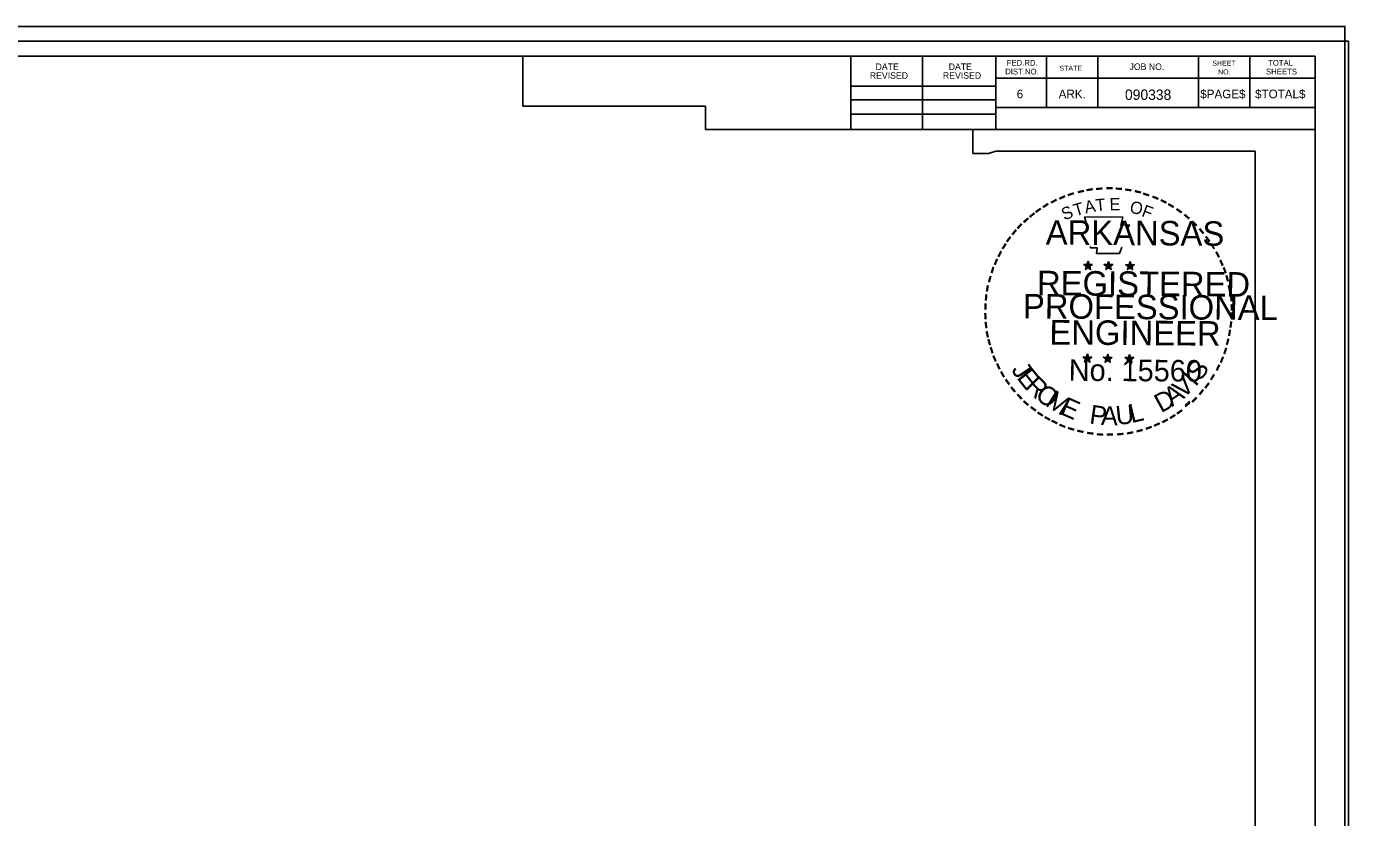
# Model space of a CAD drawing. Extents: x -3.6 to 32.1, y -0.4 to 20.9.
# Drawn here: x 14.23 to 32.07, y 10.27 to 20.95 of the extents above; entities that cross this region are included whole.
import ezdxf

# ---------------------------------------------------------------- set-up
doc = ezdxf.new("R2010")
doc.units = 0
for name, color, linetype in [('Level 1', 7, 'Continuous'), ('Level 62', 7, 'Continuous'), ('Level 63', 7, 'Continuous'), ('Level 63 Full', 7, 'Continuous'), ('R_Border', 7, 'Continuous'), ('R_Border Prelim', 7, 'Continuous')]:
    doc.layers.add(name, color=color, linetype=linetype)

msp = doc.modelspace()

# ---------------------------------------------------------------- linework, layer by layer
at = {"layer": 'Level 1'}
for p, q in [((-0.001, 20.545), (31.617, 20.545)), ((25.353, 19.557), (25.353, 20.545)), ((26.321, 19.557), (26.321, 20.545)), ((27.307, 20.545), (27.307, 19.557)), ((27.991, 20.545), (27.991, 19.851)), ((28.685, 20.545), (28.685, 19.851)), ((30.043, 20.545), (30.043, 19.851)), ((30.737, 20.545), (30.737, 19.851)), ((31.617, -0.001), (31.617, 20.545)), ((31.617, 20.251), (27.307, 20.251)), ((31.617, 20.253), (31.617, 20.253)), ((25.353, 20.143), (27.307, 20.143)), ((25.353, 19.957), (27.307, 19.957)), ((31.617, 19.851), (27.307, 19.851)), ((27.603, 19.851), (31.617, 19.851)), ((25.353, 19.763), (27.307, 19.763)), ((31.617, 19.557), (25.353, 19.557))]:
    msp.add_line(p, q, dxfattribs=at)
at = {"layer": 'Level 62'}
for p, q in [((23.392, 19.558), (23.391, 19.872)), ((27, 19.558), (23.392, 19.558)), ((27, 19.233), (27, 19.558)), ((27.308, 19.266), (27.212, 19.233)), ((30.808, 19.265), (27.308, 19.266)), ((30.808, 9.545), (30.808, 19.265)), ((30.808, 19.265), (30.808, 19.265)), ((27.212, 19.233), (27, 19.233))]:
    msp.add_line(p, q, dxfattribs=at)
msp.add_lwpolyline([(23.391, 19.872), (20.927, 19.872), (20.927, 20.544), (0.808, 20.545)], dxfattribs=at)
at = {"layer": 'Level 63'}
msp.add_lwpolyline([(-1.263, -0.2), (32.067, -0.2), (32.067, 20.746), (-1.263, 20.746)], close=True, dxfattribs=at)
at = {"layer": 'Level 63 Full'}
msp.add_lwpolyline([(32.017, -0.403), (-3.583, -0.403), (-3.583, 20.947), (32.017, 20.947)], close=True, dxfattribs=at)
at = {"layer": 'R_Border Prelim'}
for p, q in [((28.494, 17.736), (28.553, 17.718)), ((28.494, 17.736), (28.537, 17.734)), ((28.494, 17.736), (28.537, 17.732)), ((28.494, 17.736), (28.533, 17.726)), ((28.494, 17.736), (28.533, 17.72)), ((28.494, 17.736), (28.533, 17.718)), ((28.494, 17.736), (28.533, 17.712)), ((28.518, 17.669), (28.553, 17.718)), ((28.518, 17.669), (28.533, 17.716)), ((28.518, 17.669), (28.537, 17.709)), ((28.518, 17.669), (28.539, 17.707)), ((28.518, 17.669), (28.545, 17.703)), ((28.518, 17.669), (28.553, 17.703)), ((28.518, 17.669), (28.553, 17.699)), ((28.553, 17.781), (28.545, 17.736)), ((28.553, 17.781), (28.545, 17.74)), ((28.553, 17.781), (28.549, 17.74)), ((28.553, 17.718), (28.553, 17.781)), ((28.553, 17.781), (28.563, 17.736)), ((28.553, 17.781), (28.561, 17.74)), ((28.553, 17.781), (28.555, 17.74)), ((28.61, 17.736), (28.553, 17.718)), ((28.588, 17.667), (28.553, 17.718)), ((28.588, 17.667), (28.553, 17.703)), ((28.588, 17.667), (28.553, 17.699)), ((28.61, 17.736), (28.557, 17.732)), ((28.588, 17.667), (28.557, 17.703)), ((28.61, 17.736), (28.563, 17.728)), ((28.61, 17.736), (28.563, 17.724)), ((28.588, 17.667), (28.563, 17.716)), ((28.588, 17.667), (28.563, 17.709)), ((28.588, 17.667), (28.569, 17.718)), ((28.61, 17.736), (28.571, 17.724)), ((28.61, 17.736), (28.578, 17.72)), ((28.61, 17.736), (28.58, 17.718)), ((28.769, 17.734), (28.828, 17.718)), ((28.769, 17.734), (28.812, 17.732)), ((28.769, 17.734), (28.812, 17.728)), ((28.769, 17.734), (28.812, 17.726)), ((28.769, 17.734), (28.81, 17.718)), ((28.769, 17.734), (28.81, 17.716)), ((28.769, 17.734), (28.81, 17.709)), ((28.794, 17.667), (28.828, 17.718)), ((28.794, 17.667), (28.812, 17.712)), ((28.794, 17.667), (28.812, 17.709)), ((28.794, 17.667), (28.814, 17.707)), ((28.794, 17.667), (28.82, 17.701)), ((28.794, 17.667), (28.828, 17.701)), ((28.794, 17.667), (28.828, 17.699)), ((28.828, 17.777), (28.82, 17.734)), ((28.828, 17.777), (28.82, 17.736)), ((28.828, 17.777), (28.822, 17.736)), ((28.828, 17.718), (28.828, 17.777)), ((28.828, 17.777), (28.839, 17.734)), ((28.828, 17.777), (28.837, 17.736)), ((28.828, 17.777), (28.831, 17.736)), ((28.886, 17.734), (28.828, 17.718)), ((28.863, 17.667), (28.828, 17.718)), ((28.863, 17.667), (28.828, 17.701)), ((28.863, 17.667), (28.828, 17.699)), ((28.886, 17.734), (28.835, 17.732)), ((28.863, 17.667), (28.835, 17.701)), ((28.886, 17.734), (28.839, 17.726)), ((28.886, 17.734), (28.839, 17.724)), ((28.863, 17.667), (28.839, 17.716)), ((28.863, 17.667), (28.839, 17.707)), ((28.863, 17.667), (28.845, 17.716)), ((28.886, 17.734), (28.847, 17.72)), ((28.886, 17.734), (28.853, 17.718)), ((28.886, 17.734), (28.855, 17.716)), ((29.061, 17.732), (29.12, 17.712)), ((29.061, 17.732), (29.108, 17.726)), ((29.061, 17.732), (29.104, 17.724)), ((29.061, 17.732), (29.104, 17.72)), ((29.061, 17.732), (29.102, 17.716)), ((29.061, 17.732), (29.102, 17.709)), ((29.061, 17.732), (29.102, 17.709)), ((29.083, 17.665), (29.12, 17.712)), ((29.083, 17.665), (29.104, 17.709)), ((29.083, 17.665), (29.108, 17.703)), ((29.083, 17.665), (29.108, 17.701)), ((29.083, 17.665), (29.12, 17.701)), ((29.083, 17.665), (29.116, 17.699)), ((29.083, 17.665), (29.124, 17.693)), ((29.12, 17.773), (29.11, 17.734)), ((29.12, 17.773), (29.116, 17.732)), ((29.12, 17.773), (29.116, 17.732)), ((29.12, 17.712), (29.12, 17.773)), ((29.12, 17.773), (29.132, 17.732)), ((29.12, 17.773), (29.128, 17.732)), ((29.12, 17.773), (29.124, 17.732)), ((29.177, 17.732), (29.12, 17.712)), ((29.153, 17.665), (29.12, 17.712)), ((29.153, 17.665), (29.12, 17.701)), ((29.153, 17.665), (29.12, 17.693)), ((29.177, 17.732), (29.126, 17.726)), ((29.153, 17.665), (29.126, 17.699)), ((29.177, 17.732), (29.132, 17.724)), ((29.177, 17.732), (29.132, 17.718)), ((29.153, 17.665), (29.132, 17.709)), ((29.153, 17.665), (29.132, 17.703)), ((29.153, 17.665), (29.137, 17.709)), ((29.177, 17.732), (29.141, 17.716)), ((29.177, 17.732), (29.143, 17.716)), ((29.177, 17.732), (29.149, 17.712)), ((28.486, 16.483), (28.545, 16.465)), ((28.486, 16.483), (28.529, 16.481)), ((28.486, 16.483), (28.527, 16.475)), ((28.486, 16.483), (28.527, 16.475)), ((28.486, 16.483), (28.527, 16.467)), ((28.486, 16.483), (28.527, 16.465)), ((28.486, 16.483), (28.527, 16.463)), ((28.506, 16.42), (28.545, 16.465)), ((28.506, 16.42), (28.527, 16.465)), ((28.506, 16.42), (28.529, 16.457)), ((28.506, 16.42), (28.531, 16.457)), ((28.506, 16.42), (28.545, 16.455)), ((28.506, 16.42), (28.537, 16.451)), ((28.506, 16.42), (28.545, 16.449)), ((28.545, 16.528), (28.533, 16.488)), ((28.545, 16.528), (28.537, 16.483)), ((28.545, 16.528), (28.539, 16.483)), ((28.578, 16.416), (28.541, 16.449)), ((28.545, 16.465), (28.545, 16.528)), ((28.545, 16.528), (28.553, 16.483)), ((28.545, 16.528), (28.553, 16.483)), ((28.545, 16.528), (28.545, 16.483)), ((28.602, 16.483), (28.545, 16.465)), ((28.578, 16.416), (28.545, 16.465)), ((28.578, 16.416), (28.545, 16.451)), ((28.578, 16.416), (28.547, 16.451)), ((28.602, 16.483), (28.549, 16.481)), ((28.602, 16.483), (28.553, 16.475)), ((28.602, 16.483), (28.553, 16.473)), ((28.578, 16.416), (28.553, 16.465)), ((28.578, 16.416), (28.553, 16.457)), ((28.602, 16.483), (28.561, 16.471)), ((28.578, 16.416), (28.561, 16.465)), ((28.602, 16.483), (28.565, 16.467)), ((28.602, 16.483), (28.569, 16.465)), ((28.761, 16.483), (28.82, 16.465)), ((28.761, 16.483), (28.804, 16.479)), ((28.761, 16.483), (28.804, 16.475)), ((28.761, 16.483), (28.804, 16.473)), ((28.761, 16.483), (28.802, 16.467)), ((28.761, 16.483), (28.802, 16.463)), ((28.761, 16.483), (28.802, 16.459)), ((28.782, 16.416), (28.82, 16.465)), ((28.782, 16.416), (28.804, 16.463)), ((28.782, 16.416), (28.804, 16.455)), ((28.782, 16.416), (28.806, 16.455)), ((28.782, 16.416), (28.812, 16.451)), ((28.782, 16.416), (28.82, 16.451)), ((28.782, 16.416), (28.82, 16.447)), ((28.82, 16.524), (28.81, 16.483)), ((28.82, 16.524), (28.812, 16.483)), ((28.82, 16.524), (28.814, 16.483)), ((28.853, 16.416), (28.818, 16.447)), ((28.82, 16.465), (28.82, 16.524)), ((28.82, 16.524), (28.828, 16.481)), ((28.82, 16.524), (28.828, 16.481)), ((28.82, 16.524), (28.82, 16.483)), ((28.875, 16.481), (28.82, 16.465)), ((28.853, 16.416), (28.82, 16.465)), ((28.853, 16.416), (28.82, 16.451)), ((28.853, 16.416), (28.822, 16.451)), ((28.875, 16.481), (28.826, 16.481)), ((28.875, 16.481), (28.828, 16.473)), ((28.875, 16.481), (28.828, 16.473)), ((28.853, 16.416), (28.828, 16.463)), ((28.853, 16.416), (28.828, 16.457)), ((28.875, 16.481), (28.837, 16.467)), ((28.853, 16.416), (28.837, 16.463)), ((28.875, 16.481), (28.843, 16.465)), ((28.875, 16.481), (28.845, 16.463)), ((29.053, 16.479), (29.112, 16.459)), ((29.053, 16.479), (29.096, 16.475)), ((29.053, 16.479), (29.096, 16.471)), ((29.053, 16.479), (29.094, 16.467)), ((29.053, 16.479), (29.094, 16.463)), ((29.053, 16.479), (29.092, 16.459)), ((29.053, 16.479), (29.092, 16.455)), ((29.075, 16.412), (29.112, 16.459)), ((29.075, 16.412), (29.094, 16.459)), ((29.075, 16.412), (29.096, 16.451)), ((29.075, 16.412), (29.1, 16.451)), ((29.075, 16.412), (29.104, 16.447)), ((29.075, 16.412), (29.11, 16.447)), ((29.075, 16.412), (29.112, 16.443)), ((29.112, 16.522), (29.102, 16.479)), ((29.112, 16.522), (29.104, 16.479)), ((29.112, 16.522), (29.108, 16.479)), ((29.145, 16.412), (29.11, 16.447)), ((29.145, 16.412), (29.11, 16.443)), ((29.112, 16.459), (29.112, 16.522)), ((29.112, 16.522), (29.12, 16.479)), ((29.112, 16.522), (29.12, 16.479)), ((29.112, 16.522), (29.112, 16.479)), ((29.169, 16.479), (29.112, 16.459)), ((29.145, 16.412), (29.112, 16.459)), ((29.145, 16.412), (29.116, 16.447)), ((29.169, 16.479), (29.118, 16.475)), ((29.169, 16.479), (29.12, 16.471)), ((29.169, 16.479), (29.12, 16.467)), ((29.145, 16.412), (29.12, 16.451)), ((29.145, 16.412), (29.124, 16.459)), ((29.145, 16.412), (29.126, 16.459)), ((29.169, 16.479), (29.132, 16.465)), ((29.169, 16.479), (29.134, 16.459)), ((29.169, 16.479), (29.137, 16.459))]:
    msp.add_line(p, q, dxfattribs=at)
for points in [[(28.506, 18.379), (28.547, 18.24)], [(29.086, 18.222), (29.11, 18.27), (28.994, 18.264), (29.02, 18.375), (28.506, 18.379)], [(28.586, 17.977), (28.586, 17.96), (28.678, 17.958), (28.669, 17.883), (28.977, 17.881), (29.01, 17.967)], [(28.553, 17.781), (28.588, 17.667), (28.494, 17.736), (28.61, 17.736), (28.518, 17.669), (28.553, 17.781)], [(28.828, 17.777), (28.863, 17.667), (28.769, 17.734), (28.886, 17.734), (28.794, 17.667), (28.828, 17.777)], [(29.12, 17.773), (29.153, 17.665), (29.061, 17.732), (29.177, 17.732), (29.083, 17.665), (29.12, 17.773)], [(28.545, 16.528), (28.578, 16.416), (28.486, 16.483), (28.602, 16.483), (28.506, 16.42), (28.545, 16.528)], [(28.82, 16.524), (28.853, 16.416), (28.761, 16.483), (28.875, 16.481), (28.782, 16.416), (28.82, 16.524)], [(29.112, 16.522), (29.145, 16.412), (29.053, 16.479), (29.169, 16.479), (29.075, 16.412), (29.112, 16.522)], [(29.877, 15.816), (29.869, 15.843), (29.918, 15.884)], [(29.914, 15.89), (29.922, 15.865), (29.873, 15.822)], [(29.922, 15.869), (29.873, 15.827)], [(29.922, 15.865), (29.875, 15.825)]]:
    msp.add_lwpolyline(points, dxfattribs=at)
for centre, radius in [((28.554, 17.717), 0.0285), ((28.554, 17.717), 0.0258), ((28.554, 17.717), 0.0239), ((28.554, 17.717), 0.0219), ((28.554, 17.717), 0.0191), ((28.554, 17.717), 0.0178), ((28.554, 17.717), 0.0164), ((28.554, 17.717), 0.0141), ((28.554, 17.717), 0.0124), ((28.554, 17.717), 0.0103), ((28.554, 17.717), 0.00819), ((28.554, 17.717), 0.00611), ((28.554, 17.717), 0.0049), ((28.554, 17.717), 0.00238), ((28.83, 17.715), 0.0285), ((28.83, 17.715), 0.0258), ((28.83, 17.715), 0.0239), ((28.83, 17.715), 0.0219), ((28.83, 17.715), 0.0191), ((28.83, 17.715), 0.0178), ((28.83, 17.715), 0.0164), ((28.83, 17.715), 0.0141), ((28.83, 17.715), 0.0124), ((28.83, 17.715), 0.0103), ((28.83, 17.715), 0.00819), ((28.83, 17.715), 0.00611), ((28.83, 17.715), 0.0049), ((28.83, 17.715), 0.00238), ((29.122, 17.711), 0.0285), ((29.122, 17.711), 0.0258), ((29.122, 17.711), 0.0239), ((29.122, 17.711), 0.0219), ((29.122, 17.711), 0.0191), ((29.122, 17.711), 0.0178), ((29.122, 17.711), 0.0164), ((29.122, 17.711), 0.0141), ((29.122, 17.711), 0.0124), ((29.122, 17.711), 0.0103), ((29.122, 17.711), 0.00819), ((29.122, 17.711), 0.00611), ((29.122, 17.711), 0.0049), ((29.122, 17.711), 0.00238), ((28.545, 16.465), 0.0285), ((28.545, 16.465), 0.0258), ((28.545, 16.465), 0.0239), ((28.545, 16.465), 0.0219), ((28.545, 16.465), 0.0191), ((28.545, 16.465), 0.0178), ((28.545, 16.465), 0.0164), ((28.545, 16.465), 0.0141), ((28.545, 16.465), 0.0124), ((28.545, 16.465), 0.0103), ((28.545, 16.465), 0.00819), ((28.545, 16.465), 0.00611), ((28.545, 16.465), 0.0049), ((28.545, 16.465), 0.00238), ((28.821, 16.463), 0.0285), ((28.821, 16.463), 0.0258), ((28.821, 16.463), 0.0239), ((28.821, 16.463), 0.0219), ((28.821, 16.463), 0.0191), ((28.821, 16.463), 0.0178), ((28.821, 16.463), 0.0164), ((28.821, 16.463), 0.0141), ((28.821, 16.463), 0.0124), ((28.821, 16.463), 0.0103), ((28.821, 16.463), 0.00819), ((28.821, 16.463), 0.00611), ((28.821, 16.463), 0.0049), ((28.821, 16.463), 0.00238), ((29.113, 16.459), 0.0285), ((29.113, 16.459), 0.0258), ((29.113, 16.459), 0.0239), ((29.113, 16.459), 0.0219), ((29.113, 16.459), 0.0191), ((29.113, 16.459), 0.0178), ((29.113, 16.459), 0.0164), ((29.113, 16.459), 0.0141), ((29.113, 16.459), 0.0124), ((29.113, 16.459), 0.0103), ((29.113, 16.459), 0.00819), ((29.113, 16.459), 0.00611), ((29.113, 16.459), 0.0049), ((29.113, 16.459), 0.00238)]:
    msp.add_circle(centre, radius, dxfattribs=at)

# ---------------------------------------------------------------- texts
at = {"layer": 'Level 1'}
for s, height, p in [('DATE', 0.0879, (25.687, 20.359)), ('DATE', 0.0879, (26.673, 20.359)), ('DIST.NO.', 0.0782, (27.435, 20.299)), ('FED.RD.', 0.0782, (27.455, 20.417)), ('STATE', 0.0684, (28.167, 20.349)), ('JOB NO.', 0.0879, (29.112, 20.36)), ('SHEET', 0.0684, (30.229, 20.417)), ('NO.', 0.0684, (30.307, 20.299)), ('SHEETS', 0.0782, (30.953, 20.299)), ('TOTAL', 0.0782, (30.981, 20.417)), ('REVISED', 0.0879, (25.609, 20.241)), ('REVISED', 0.0879, (26.595, 20.241)), ('6', 0.117, (27.591, 19.977)), ('ARK.', 0.1172, (28.157, 19.977)), ('090338', 0.14, (29.051, 19.956)), ('$PAGE$', 0.1172, (30.067, 19.977)), ('$TOTAL$', 0.1172, (30.806, 19.977))]:
    msp.add_text(s, height=height, dxfattribs=at).set_placement(p)
at = {"layer": 'R_Border'}
msp.add_text('JOB NO.', height=0.0879, dxfattribs=at).set_placement((29.112, 20.36))
at = {"layer": 'R_Border Prelim'}
for s, height, rotation, p in [('-', 0.264, 13.2326, (28.423, 18.607)), ('-', 0.264, 9.8217, (28.533, 18.634)), ('-', 0.264, 5.4992, (28.655, 18.65)), ('-', 0.264, 359.7886, (28.782, 18.662)), ('-', 0.264, 357.3454, (28.904, 18.658)), ('-', 0.264, 351.7641, (29.024, 18.648)), ('-', 0.264, 346.8073, (29.145, 18.63)), ('-', 0.264, 33.666, (27.988, 18.413)), ('-', 0.264, 28.3942, (28.088, 18.472)), ('-', 0.264, 23.9096, (28.192, 18.523)), ('-', 0.264, 18.7785, (28.298, 18.568)), ('T', 0.165, 16.006, (28.382, 18.383)), ('A', 0.165, 10.8156, (28.52, 18.423)), ('T', 0.165, 5.6252, (28.661, 18.45)), ('E', 0.165, 0.4347, (28.843, 18.466)), ('O', 0.165, 350.0539, (29.108, 18.432)), ('-', 0.264, 341.9386, (29.249, 18.601)), ('-', 0.264, 337.4575, (29.369, 18.564)), ('-', 0.264, 333.7235, (29.475, 18.521)), ('-', 0.264, 329.2433, (29.569, 18.472)), ('-', 0.264, 42.5646, (27.741, 18.217)), ('-', 0.264, 38.5531, (27.815, 18.285)), ('-', 0.264, 35.8341, (27.892, 18.348)), ('S', 0.165, 21.1964, (28.231, 18.328)), ('F', 0.165, 339.6731, (29.265, 18.391)), ('-', 0.264, 325.4651, (29.675, 18.409)), ('-', 0.264, 320.1321, (29.775, 18.34)), ('-', 0.264, 50.2166, (27.598, 18.06)), ('-', 0.264, 48.0254, (27.666, 18.14)), ('ARKANSAS', 0.3306, 359.6024, (27.982, 18.003)), ('-', 0.264, 315.181, (29.875, 18.258)), ('-', 0.264, 309.4821, (29.967, 18.166)), ('-', 0.264, 57.673, (27.476, 17.877)), ('-', 0.264, 53.8349, (27.529, 17.967)), ('-', 0.264, 306.2546, (30.05, 18.066)), ('-', 0.231, 303.2777, (30.132, 17.971)), ('-', 0.264, 62.4738, (27.425, 17.777)), ('-', 0.264, 299.2708, (30.183, 17.871)), ('-', 0.264, 71.9969, (27.343, 17.573)), ('-', 0.264, 67.3767, (27.382, 17.677)), ('-', 0.264, 294.2652, (30.236, 17.769)), ('-', 0.264, 290.1752, (30.281, 17.677)), ('-', 0.264, 75.0634, (27.311, 17.454)), ('REGISTERED', 0.3306, 359.6024, (27.864, 17.32)), ('-', 0.264, 284.7257, (30.316, 17.579)), ('-', 0.264, 84.7887, (27.274, 17.224)), ('-', 0.264, 80.8037, (27.286, 17.338)), ('PROFESSIONAL', 0.33055, 359.6024, (27.674, 17.008)), ('-', 0.264, 280.1517, (30.348, 17.454)), ('-', 0.264, 276.1986, (30.377, 17.328)), ('-', 0.264, 88.6646, (27.27, 17.108)), ('-', 0.264, 273.9325, (30.385, 17.208)), ('-', 0.264, 93.7983, (27.274, 16.987)), ('-', 0.264, 98.5503, (27.286, 16.875)), ('ENGINEER', 0.3306, 359.6024, (28.031, 16.655)), ('-', 0.264, 263.1196, (30.385, 16.995)), ('-', 0.264, 269.5431, (30.389, 17.106)), ('-', 0.264, 101.3173, (27.305, 16.755)), ('-', 0.264, 260.5977, (30.371, 16.887)), ('-', 0.264, 105.0602, (27.333, 16.657)), ('-', 0.264, 108.6898, (27.368, 16.555)), ('-', 0.264, 252.4705, (30.324, 16.655)), ('-', 0.264, 255.365, (30.352, 16.775)), ('-', 0.264, 113.6667, (27.409, 16.453)), ('No. 15560', 0.2909, 359.6024, (28.292, 16.166)), ('S', 0.255, 53.5227, (30.065, 16.15)), ('-', 0.264, 247.4911, (30.287, 16.543)), ('-', 0.264, 115.3313, (27.46, 16.351)), ('-', 0.264, 120.0495, (27.517, 16.253)), ('J', 0.255, 303.9209, (27.51, 16.312)), ('E', 0.255, 308.618, (27.582, 16.205)), ('R', 0.255, 314.7784, (27.688, 16.075)), ('V', 0.255, 41.4844, (29.833, 15.917)), ('I', 0.255, 49.9999, (30.002, 16.077)), ('-', 0.264, 238.6736, (30.175, 16.318)), ('-', 0.264, 244.2221, (30.24, 16.441)), ('-', 0.264, 125.4958, (27.584, 16.161)), ('-', 0.264, 130.3205, (27.658, 16.069)), ('O', 0.255, 321.6761, (27.824, 15.944)), ('A', 0.255, 34.8903, (29.687, 15.811)), ('-', 0.264, 233.4476, (30.034, 16.12)), ('-', 0.264, 233.4476, (30.112, 16.21)), ('-', 0.264, 133.8262, (27.743, 15.98)), ('-', 0.264, 138.5362, (27.827, 15.902)), ('M', 0.255, 328.1357, (27.964, 15.837)), ('E', 0.255, 336.4966, (28.161, 15.722)), ('D', 0.255, 28.5809, (29.537, 15.727)), ('-', 0.264, 225.3677, (29.957, 16.024)), ('-', 0.264, 144.2487, (27.923, 15.835)), ('-', 0.264, 147.6922, (28.012, 15.771)), ('P', 0.255, 351.9783, (28.563, 15.591)), ('A', 0.255, 357.9896, (28.725, 15.57)), ('U', 0.255, 5.7635, (28.938, 15.568)), ('L', 0.255, 13.0992, (29.137, 15.593)), ('-', 0.264, 211.8515, (29.689, 15.8)), ('-', 0.264, 215.3387, (29.777, 15.863)), ('-', 0.264, 151.1728, (28.106, 15.718)), ('-', 0.264, 154.2026, (28.196, 15.676)), ('-', 0.264, 158.1636, (28.298, 15.631)), ('-', 0.264, 162.4007, (28.412, 15.596)), ('-', 0.264, 195.0767, (29.279, 15.606)), ('-', 0.264, 200.3208, (29.392, 15.647)), ('-', 0.264, 203.854, (29.494, 15.692)), ('-', 0.264, 206.9592, (29.598, 15.743)), ('-', 0.264, 167.1579, (28.529, 15.57)), ('-', 0.264, 172.7179, (28.655, 15.551)), ('-', 0.264, 176.1207, (28.78, 15.539)), ('-', 0.264, 181.1942, (28.902, 15.543)), ('-', 0.264, 185.4191, (29.037, 15.553)), ('-', 0.264, 190.8882, (29.159, 15.574))]:
    msp.add_text(s, height=height, rotation=rotation, dxfattribs=at).set_placement(p)

doc.saveas('drawing.dxf')
